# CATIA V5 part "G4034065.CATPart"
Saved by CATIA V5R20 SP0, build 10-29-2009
Part number: G4034065
Revision: 5
Definition: design
Nomenclature: G4034065
Source: made
Description: NOT SPECIFIED
Bounding box of the stored display mesh (mm): x -32 to 33, y -25.81 to 25.81, z -26 to 26
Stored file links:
  C:\Users\Raffaele\Desktop\3D X SITO CF\BOLEX\27-BUSH REF 403\G4034065.CATPart
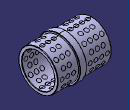
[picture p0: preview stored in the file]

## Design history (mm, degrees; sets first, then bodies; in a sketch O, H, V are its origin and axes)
Body1 "MANIFOLD_SOLID_BREP #14163" (main body)
  Solid1: solid without history
Body2 "MANIFOLD_SOLID_BREP #14318"
  Solid2: solid without history
Body3 "MANIFOLD_SOLID_BREP #14473"
  Solid3: solid without history
Body4 "MANIFOLD_SOLID_BREP #14628"
  Solid4: solid without history
Body5 "MANIFOLD_SOLID_BREP #14783"
  Solid5: solid without history
Body6 "MANIFOLD_SOLID_BREP #14938"
  Solid6: solid without history
Body7 "MANIFOLD_SOLID_BREP #15093"
  Solid7: solid without history
Body8 "MANIFOLD_SOLID_BREP #15250"
  Solid8: solid without history
Body9 "MANIFOLD_SOLID_BREP #15407"
  Solid9: solid without history
Body10 "MANIFOLD_SOLID_BREP #15562"
  Solid10: solid without history
Body11 "MANIFOLD_SOLID_BREP #15717"
  Solid11: solid without history
Body12 "MANIFOLD_SOLID_BREP #15872"
  Solid12: solid without history
Body13 "MANIFOLD_SOLID_BREP #16027"
  Solid13: solid without history
Body14 "MANIFOLD_SOLID_BREP #16184"
  Solid14: solid without history
Body15 "MANIFOLD_SOLID_BREP #16341"
  Solid15: solid without history
Body16 "MANIFOLD_SOLID_BREP #16496"
  Solid16: solid without history
Body17 "MANIFOLD_SOLID_BREP #16651"
  Solid17: solid without history
Body18 "MANIFOLD_SOLID_BREP #16808"
  Solid18: solid without history
Body19 "MANIFOLD_SOLID_BREP #16965"
  Solid19: solid without history
Body20 "MANIFOLD_SOLID_BREP #17122"
  Solid20: solid without history
Body21 "MANIFOLD_SOLID_BREP #17279"
  Solid21: solid without history
Body22 "MANIFOLD_SOLID_BREP #17436"
  Solid22: solid without history
Body23 "MANIFOLD_SOLID_BREP #17593"
  Solid23: solid without history
Body24 "MANIFOLD_SOLID_BREP #17750"
  Solid24: solid without history
Body25 "MANIFOLD_SOLID_BREP #17907"
  Solid25: solid without history
Body26 "MANIFOLD_SOLID_BREP #18062"
  Solid26: solid without history
Body27 "MANIFOLD_SOLID_BREP #18219"
  Solid27: solid without history
Body28 "MANIFOLD_SOLID_BREP #18374"
  Solid28: solid without history
Body29 "MANIFOLD_SOLID_BREP #18529"
  Solid29: solid without history
Body30 "MANIFOLD_SOLID_BREP #18686"
  Solid30: solid without history
Body31 "MANIFOLD_SOLID_BREP #18841"
  Solid31: solid without history
Body32 "MANIFOLD_SOLID_BREP #18996"
  Solid32: solid without history
Body33 "MANIFOLD_SOLID_BREP #19151"
  Solid33: solid without history
Body34 "MANIFOLD_SOLID_BREP #19306"
  Solid34: solid without history
Body35 "MANIFOLD_SOLID_BREP #19461"
  Solid35: solid without history
Body36 "MANIFOLD_SOLID_BREP #19618"
  Solid36: solid without history
Body37 "MANIFOLD_SOLID_BREP #19775"
  Solid37: solid without history
Body38 "MANIFOLD_SOLID_BREP #19930"
  Solid38: solid without history
Body39 "MANIFOLD_SOLID_BREP #20085"
  Solid39: solid without history
Body40 "MANIFOLD_SOLID_BREP #20240"
  Solid40: solid without history
Body41 "MANIFOLD_SOLID_BREP #20395"
  Solid41: solid without history
Body42 "MANIFOLD_SOLID_BREP #20552"
  Solid42: solid without history
Body43 "MANIFOLD_SOLID_BREP #20709"
  Solid43: solid without history
Body44 "MANIFOLD_SOLID_BREP #20864"
  Solid44: solid without history
Body45 "MANIFOLD_SOLID_BREP #21019"
  Solid45: solid without history
Body46 "MANIFOLD_SOLID_BREP #21176"
  Solid46: solid without history
Body47 "MANIFOLD_SOLID_BREP #21333"
  Solid47: solid without history
Body48 "MANIFOLD_SOLID_BREP #21490"
  Solid48: solid without history
Body49 "MANIFOLD_SOLID_BREP #21647"
  Solid49: solid without history
Body50 "MANIFOLD_SOLID_BREP #21804"
  Solid50: solid without history
Body51 "MANIFOLD_SOLID_BREP #21961"
  Solid51: solid without history
Body52 "MANIFOLD_SOLID_BREP #22118"
  Solid52: solid without history
Body53 "MANIFOLD_SOLID_BREP #22275"
  Solid53: solid without history
Body54 "MANIFOLD_SOLID_BREP #22430"
  Solid54: solid without history
Body55 "MANIFOLD_SOLID_BREP #22585"
  Solid55: solid without history
Body56 "MANIFOLD_SOLID_BREP #22740"
  Solid56: solid without history
Body57 "MANIFOLD_SOLID_BREP #22895"
  Solid57: solid without history
Body58 "MANIFOLD_SOLID_BREP #23052"
  Solid58: solid without history
Body59 "MANIFOLD_SOLID_BREP #23209"
  Solid59: solid without history
Body60 "MANIFOLD_SOLID_BREP #23366"
  Solid60: solid without history
Body61 "MANIFOLD_SOLID_BREP #23523"
  Solid61: solid without history
Body62 "MANIFOLD_SOLID_BREP #23680"
  Solid62: solid without history
Body63 "MANIFOLD_SOLID_BREP #23837"
  Solid63: solid without history
Body64 "MANIFOLD_SOLID_BREP #23994"
  Solid64: solid without history
Body65 "MANIFOLD_SOLID_BREP #24151"
  Solid65: solid without history
Body66 "MANIFOLD_SOLID_BREP #24306"
  Solid66: solid without history
Body67 "MANIFOLD_SOLID_BREP #24461"
  Solid67: solid without history
Body68 "MANIFOLD_SOLID_BREP #24618"
  Solid68: solid without history
Body69 "MANIFOLD_SOLID_BREP #24775"
  Solid69: solid without history
Body70 "MANIFOLD_SOLID_BREP #24930"
  Solid70: solid without history
Body71 "MANIFOLD_SOLID_BREP #25085"
  Solid71: solid without history
Body72 "MANIFOLD_SOLID_BREP #25240"
  Solid72: solid without history
Body73 "MANIFOLD_SOLID_BREP #25395"
  Solid73: solid without history
Body74 "MANIFOLD_SOLID_BREP #25552"
  Solid74: solid without history
Body75 "MANIFOLD_SOLID_BREP #25709"
  Solid75: solid without history
Body76 "MANIFOLD_SOLID_BREP #25864"
  Solid76: solid without history
Body77 "MANIFOLD_SOLID_BREP #26019"
  Solid77: solid without history
Body78 "MANIFOLD_SOLID_BREP #26176"
  Solid78: solid without history
Body79 "MANIFOLD_SOLID_BREP #26333"
  Solid79: solid without history
Body80 "MANIFOLD_SOLID_BREP #26490"
  Solid80: solid without history
Body81 "MANIFOLD_SOLID_BREP #26647"
  Solid81: solid without history
Body82 "MANIFOLD_SOLID_BREP #26804"
  Solid82: solid without history
Body83 "MANIFOLD_SOLID_BREP #26961"
  Solid83: solid without history
Body84 "MANIFOLD_SOLID_BREP #27118"
  Solid84: solid without history
Body85 "MANIFOLD_SOLID_BREP #27275"
  Solid85: solid without history
Body86 "MANIFOLD_SOLID_BREP #27432"
  Solid86: solid without history
Body87 "MANIFOLD_SOLID_BREP #27589"
  Solid87: solid without history
Body88 "MANIFOLD_SOLID_BREP #27746"
  Solid88: solid without history
Body89 "MANIFOLD_SOLID_BREP #27903"
  Solid89: solid without history
Body90 "MANIFOLD_SOLID_BREP #28060"
  Solid90: solid without history
Body91 "MANIFOLD_SOLID_BREP #28217"
  Solid91: solid without history
Body92 "MANIFOLD_SOLID_BREP #28374"
  Solid92: solid without history
Body93 "MANIFOLD_SOLID_BREP #28531"
  Solid93: solid without history
Body94 "MANIFOLD_SOLID_BREP #28686"
  Solid94: solid without history
Body95 "MANIFOLD_SOLID_BREP #28841"
  Solid95: solid without history
Body96 "MANIFOLD_SOLID_BREP #28996"
  Solid96: solid without history
Body97 "MANIFOLD_SOLID_BREP #29151"
  Solid97: solid without history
